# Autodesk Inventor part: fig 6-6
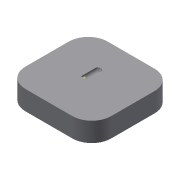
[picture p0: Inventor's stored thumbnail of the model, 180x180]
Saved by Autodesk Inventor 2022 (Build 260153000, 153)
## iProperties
Created: 2004-05
Part Number: fig 6-6
Document SubType Name: Modeling
Designer: CADCIM Technologies
Manufacturer: Standard
Standards Organization: Custom
Density: 1 g/cm^3
Material: Generic
Appearance: Default
Author: CADCIM Technologies
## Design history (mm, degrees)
sketch "Sketch1"
  geometry: L1 (0, 0)-(44.293, 0); L2 (44.293, 0)-(44.293, 42.442); L3 (44.293, 42.442)-(0, 42.442); L4 (0, 42.442)-(0, 0)
  constraints: 8 end point, 2 parallel, 1 horizontal, 1 perpendicular
extrude "Extrusion1" new body sketch "Sketch1" distance "d0" = 10; taper "d1" = 0 deg
fillet "Fillet1" dims "d2" = 10
sketch "Sketch2"
  geometry: 1 further point
sketch "Sketch3"
  geometry: L1 (10, 42.442)-(34.293, 42.442) reference; L2 (0, 10)-(0, 32.442) reference; L3 (34.293, 0)-(10, 0) reference; L4 (44.293, 32.442)-(44.293, 10) reference; A1 r 10 centre (34.293, 32.442) between (44.293, 32.442) and (34.293, 42.442) reference; A2 r 10 centre (10, 32.442) between (10, 42.442) and (0, 32.442) reference; A3 r 10 centre (10, 10) between (0, 10) and (10, 0) reference; A4 r 10 centre (34.293, 10) between (34.293, 0) and (44.293, 10) reference; 1 further point
workpoint "Work Point1"
hole "Hole4" diameter "d33" = 3; stored, may be unused: countersink angle "d37" = 90 deg, drill point angle "d39" = 118 deg; dims "d31" = 10, "d32" = 10, "d34" = 6, "d35" = 4, "d36" = 2, "d38" = 8
body "Solid1"
